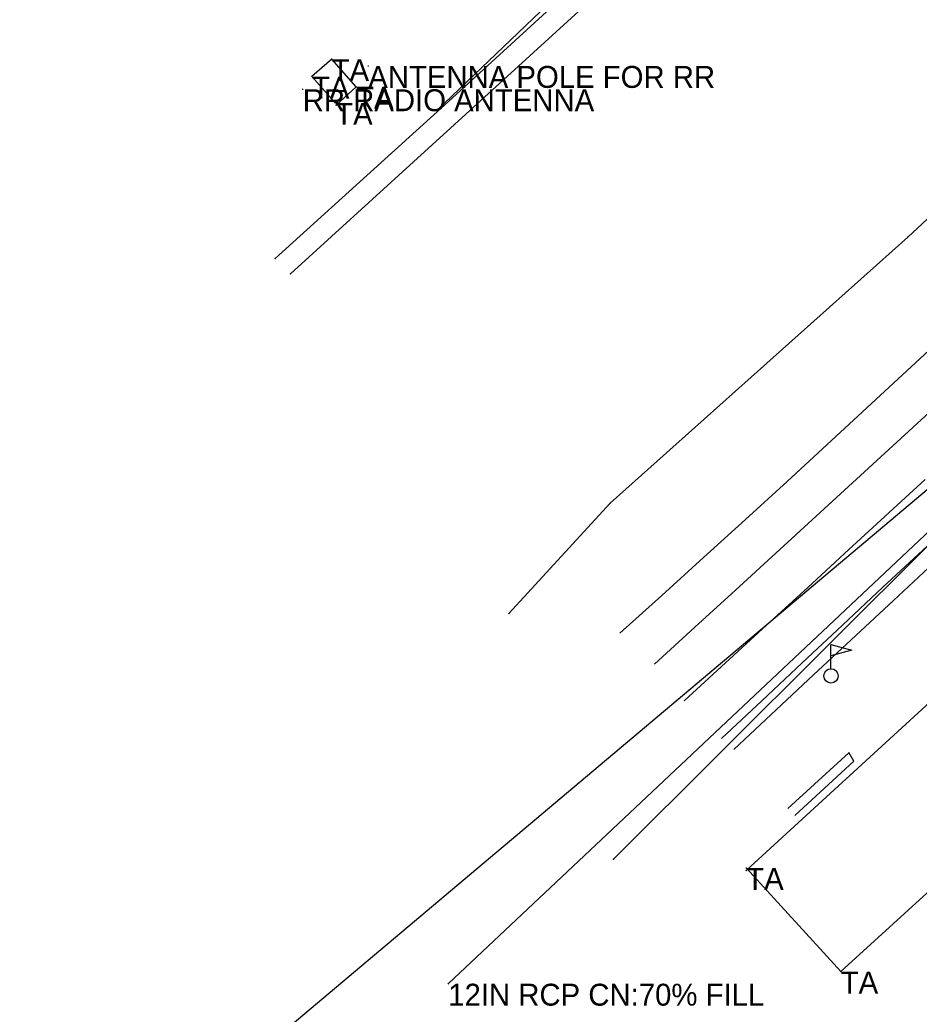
# Model space of a CAD drawing. Extents: x 1660112 to 1662239, y 668919 to 671377.
# Drawn here: x 1661239.8 to 1661444.9, y 669604.5 to 669831.4 of the extents above; entities that cross this region are included whole.
import ezdxf

# ---------------------------------------------------------------- set-up
doc = ezdxf.new("R2010")
doc.units = 0
for name, color, linetype in [('S_BASELINE', 7, 'Continuous'), ('S_BUILDING', 7, 'Continuous'), ('S_BUILDING_ANNOT', 7, 'Continuous'), ('S_CROSS_DRAIN_ANNOT', 7, 'Continuous'), ('S_DRG_PT_SYM', 7, 'Continuous'), ('S_EDGE_PAVEMENT', 7, 'Continuous'), ('S_FIBER_OPTIC_CABLE', 7, 'Continuous'), ('S_FLAG_POLE', 7, 'Continuous'), ('S_MISC_STRUCTURES_ANNOT', 7, 'Continuous'), ('S_MSC_PT_SYM', 7, 'Continuous'), ('S_PAVEMENT_CROWN', 7, 'Continuous'), ('S_RAILROAD', 7, 'Continuous'), ('S_SIDEWALK', 7, 'Continuous'), ('S_STORM_SEWER', 7, 'Continuous'), ('S_STR_PT_SYM', 7, 'Continuous'), ('S_UTL_PT_SYM', 7, 'Continuous'), ('S_WATER_UTILITIES', 7, 'Continuous')]:
    doc.layers.add(name, color=color, linetype=linetype)

msp = doc.modelspace()

# ---------------------------------------------------------------- linework, layer by layer
at = {"layer": 'S_BASELINE'}
msp.add_line((1661604.59, 669857.12), (1660827.54, 669202.71), dxfattribs=at)
at = {"layer": 'S_BUILDING'}
for p, q in [((1661310.91, 669822.41), (1661306.42, 669818.43)), ((1661316.48, 669816.12), (1661310.91, 669822.41)), ((1661306.42, 669818.43), (1661311.72, 669812.44)), ((1661311.9, 669811.92), (1661316.48, 669816.12)), ((1661405.5, 669637.28), (1661453.66, 669681.54)), ((1661475.08, 669658.04), (1661427.04, 669614.25)), ((1661427.04, 669614.25), (1661405.48, 669637.9))]:
    msp.add_line(p, q, dxfattribs=at)
at = {"layer": 'S_DRG_PT_SYM'}
msp.add_lwpolyline([(1661337.5, 669611.48), (1661337.5, 669611.53), (1661337.5, 669611.48), (1661337.45, 669611.48), (1661337.5, 669611.48), (1661337.5, 669611.43), (1661337.5, 669611.48), (1661337.55, 669611.48)], dxfattribs=at)
at = {"layer": 'S_EDGE_PAVEMENT'}
for points in [[(1661376.68, 669691.45), (1661386.22, 669700.09), (1661395.75, 669708.74), (1661405.29, 669717.39), (1661414.83, 669726.04), (1661432.01, 669741.93), (1661449.2, 669757.82)], [(1661391.32, 669676.05), (1661400.72, 669684.66), (1661410.11, 669693.28), (1661419.51, 669701.9), (1661428.9, 669710.52), (1661446.3, 669726.5)]]:
    msp.add_lwpolyline(points, dxfattribs=at)
at = {"layer": 'S_FIBER_OPTIC_CABLE'}
for p, q in [((1661442.32, 669781.84), (1661490.21, 669826.26)), ((1661374.46, 669721.09), (1661442.32, 669781.84)), ((1661351.35, 669695.93), (1661374.46, 669721.09))]:
    msp.add_line(p, q, dxfattribs=at)
at = {"layer": 'S_FLAG_POLE'}
for p, q in [((1661424.81, 669683.33), (1661424.81, 669688.88)), ((1661424.81, 669688.88), (1661429.58, 669687.6)), ((1661429.58, 669687.6), (1661424.81, 669686.32))]:
    msp.add_line(p, q, dxfattribs=at)
msp.add_circle((1661424.81, 669681.71), 1.63, dxfattribs=at)
at = {"layer": 'S_MSC_PT_SYM'}
for points in [[(1661319.25, 669820.87), (1661319.25, 669820.92), (1661319.25, 669820.87), (1661319.2, 669820.87), (1661319.25, 669820.87), (1661319.25, 669820.82), (1661319.25, 669820.87), (1661319.3, 669820.87)], [(1661304.3, 669815.55), (1661304.3, 669815.6), (1661304.3, 669815.55), (1661304.25, 669815.55), (1661304.3, 669815.55), (1661304.3, 669815.5), (1661304.3, 669815.55), (1661304.35, 669815.55)], [(1661334.95, 669810.8), (1661334.95, 669810.85), (1661334.95, 669810.8), (1661334.9, 669810.8), (1661334.95, 669810.8), (1661334.95, 669810.75), (1661334.95, 669810.8), (1661335, 669810.8)], [(1661335.82, 669811.18), (1661335.82, 669811.23), (1661335.82, 669811.18), (1661335.77, 669811.18), (1661335.82, 669811.18), (1661335.82, 669811.13), (1661335.82, 669811.18), (1661335.87, 669811.18)], [(1661338.9, 669807.53), (1661338.9, 669807.58), (1661338.9, 669807.53), (1661338.85, 669807.53), (1661338.9, 669807.53), (1661338.9, 669807.48), (1661338.9, 669807.53), (1661338.95, 669807.53)], [(1661298.02, 669776.98), (1661298.02, 669777.03), (1661298.02, 669776.98), (1661297.97, 669776.98), (1661298.02, 669776.98), (1661298.02, 669776.93), (1661298.02, 669776.98), (1661298.07, 669776.98)], [(1661301.5, 669773.47), (1661301.5, 669773.52), (1661301.5, 669773.47), (1661301.45, 669773.47), (1661301.5, 669773.47), (1661301.5, 669773.42), (1661301.5, 669773.47), (1661301.55, 669773.47)]]:
    msp.add_lwpolyline(points, dxfattribs=at)
at = {"layer": 'S_PAVEMENT_CROWN'}
msp.add_lwpolyline([(1661384.55, 669684.36), (1661393.78, 669692.81), (1661403.01, 669701.26), (1661412.24, 669709.71), (1661421.47, 669718.16), (1661438.95, 669734.2), (1661456.42, 669750.24)], dxfattribs=at)
at = {"layer": 'S_RAILROAD'}
for p, q in [((1661334.95, 669810.8), (1661397.52, 669870.6)), ((1661335.82, 669811.18), (1661398.98, 669869.07)), ((1661338.9, 669807.53), (1661402.43, 669865.48)), ((1661298.02, 669776.98), (1661335.82, 669811.18)), ((1661301.5, 669773.47), (1661338.9, 669807.53))]:
    msp.add_line(p, q, dxfattribs=at)
at = {"layer": 'S_SIDEWALK'}
for points in [[(1661399.81, 669667.42), (1661409.03, 669676.05), (1661418.25, 669684.68), (1661427.46, 669693.31), (1661436.68, 669701.94), (1661453.82, 669717.86), (1661470.97, 669733.78), (1661488.36, 669749.53), (1661505.75, 669765.29), (1661508.14, 669763.29)], [(1661402.62, 669664.93), (1661420.84, 669681.92), (1661439.05, 669698.91), (1661456.19, 669714.89), (1661473.33, 669730.87), (1661490.76, 669747.1), (1661508.19, 669763.33)], [(1661414.98, 669651.45), (1661428.85, 669664.15)], [(1661416.54, 669649.85), (1661430.04, 669662.24), (1661428.89, 669664.2)]]:
    msp.add_lwpolyline(points, dxfattribs=at)
at = {"layer": 'S_STORM_SEWER'}
msp.add_line((1661464.19, 669730.74), (1661337.5, 669611.48), dxfattribs=at)
at = {"layer": 'S_STR_PT_SYM'}
for points in [[(1661310.91, 669822.41), (1661310.91, 669822.46), (1661310.91, 669822.41), (1661310.86, 669822.41), (1661310.91, 669822.41), (1661310.91, 669822.36), (1661310.91, 669822.41), (1661310.96, 669822.41)], [(1661306.42, 669818.43), (1661306.42, 669818.48), (1661306.42, 669818.43), (1661306.37, 669818.43), (1661306.42, 669818.43), (1661306.42, 669818.38), (1661306.42, 669818.43), (1661306.47, 669818.43)], [(1661316.48, 669816.12), (1661316.48, 669816.17), (1661316.48, 669816.12), (1661316.43, 669816.12), (1661316.48, 669816.12), (1661316.48, 669816.07), (1661316.48, 669816.12), (1661316.53, 669816.12)], [(1661311.72, 669812.44), (1661311.72, 669812.49), (1661311.72, 669812.44), (1661311.67, 669812.44), (1661311.72, 669812.44), (1661311.72, 669812.39), (1661311.72, 669812.44), (1661311.77, 669812.44)], [(1661311.9, 669811.92), (1661311.9, 669811.97), (1661311.9, 669811.92), (1661311.85, 669811.92), (1661311.9, 669811.92), (1661311.9, 669811.87), (1661311.9, 669811.92), (1661311.95, 669811.92)], [(1661405.48, 669637.9), (1661405.48, 669637.95), (1661405.48, 669637.9), (1661405.43, 669637.9), (1661405.48, 669637.9), (1661405.48, 669637.84), (1661405.48, 669637.9), (1661405.53, 669637.9)], [(1661405.5, 669637.28), (1661405.5, 669637.33), (1661405.5, 669637.28), (1661405.45, 669637.28), (1661405.5, 669637.28), (1661405.5, 669637.23), (1661405.5, 669637.28), (1661405.55, 669637.28)], [(1661427.04, 669614.25), (1661427.04, 669614.3), (1661427.04, 669614.25), (1661426.99, 669614.25), (1661427.04, 669614.25), (1661427.04, 669614.2), (1661427.04, 669614.25), (1661427.09, 669614.25)]]:
    msp.add_lwpolyline(points, dxfattribs=at)
at = {"layer": 'S_UTL_PT_SYM'}
for points in [[(1661442.32, 669781.84), (1661442.32, 669781.89), (1661442.32, 669781.84), (1661442.27, 669781.84), (1661442.32, 669781.84), (1661442.32, 669781.79), (1661442.32, 669781.84), (1661442.37, 669781.84)], [(1661374.46, 669721.09), (1661374.46, 669721.14), (1661374.46, 669721.09), (1661374.41, 669721.09), (1661374.46, 669721.09), (1661374.46, 669721.04), (1661374.46, 669721.09), (1661374.51, 669721.09)], [(1661351.35, 669695.93), (1661351.35, 669695.98), (1661351.35, 669695.93), (1661351.3, 669695.93), (1661351.35, 669695.93), (1661351.35, 669695.88), (1661351.35, 669695.93), (1661351.4, 669695.93)], [(1661375.21, 669639.9), (1661375.21, 669639.95), (1661375.21, 669639.9), (1661375.16, 669639.9), (1661375.21, 669639.9), (1661375.21, 669639.85), (1661375.21, 669639.9), (1661375.26, 669639.9)]]:
    msp.add_lwpolyline(points, dxfattribs=at)
at = {"layer": 'S_WATER_UTILITIES'}
msp.add_line((1661448.56, 669713.08), (1661375.21, 669639.9), dxfattribs=at)

# ---------------------------------------------------------------- texts
at = {"layer": 'S_BUILDING_ANNOT'}
for p in [(1661310.91, 669817.41), (1661306.42, 669813.43), (1661316.48, 669811.12), (1661311.72, 669807.44), (1661405.48, 669632.9), (1661427.04, 669609.25)]:
    msp.add_text('TA', height=5, dxfattribs=at).set_placement(p)
at = {"layer": 'S_CROSS_DRAIN_ANNOT'}
msp.add_text('12IN RCP CN:70% FILL', height=5, dxfattribs=at).set_placement((1661337.5, 669606.48))
at = {"layer": 'S_MISC_STRUCTURES_ANNOT'}
for s, p in [('ANTENNA POLE FOR RR', (1661319.25, 669815.87)), ('RR RADIO ANTENNA', (1661304.3, 669810.55))]:
    msp.add_text(s, height=5, dxfattribs=at).set_placement(p)

doc.saveas('drawing.dxf')
